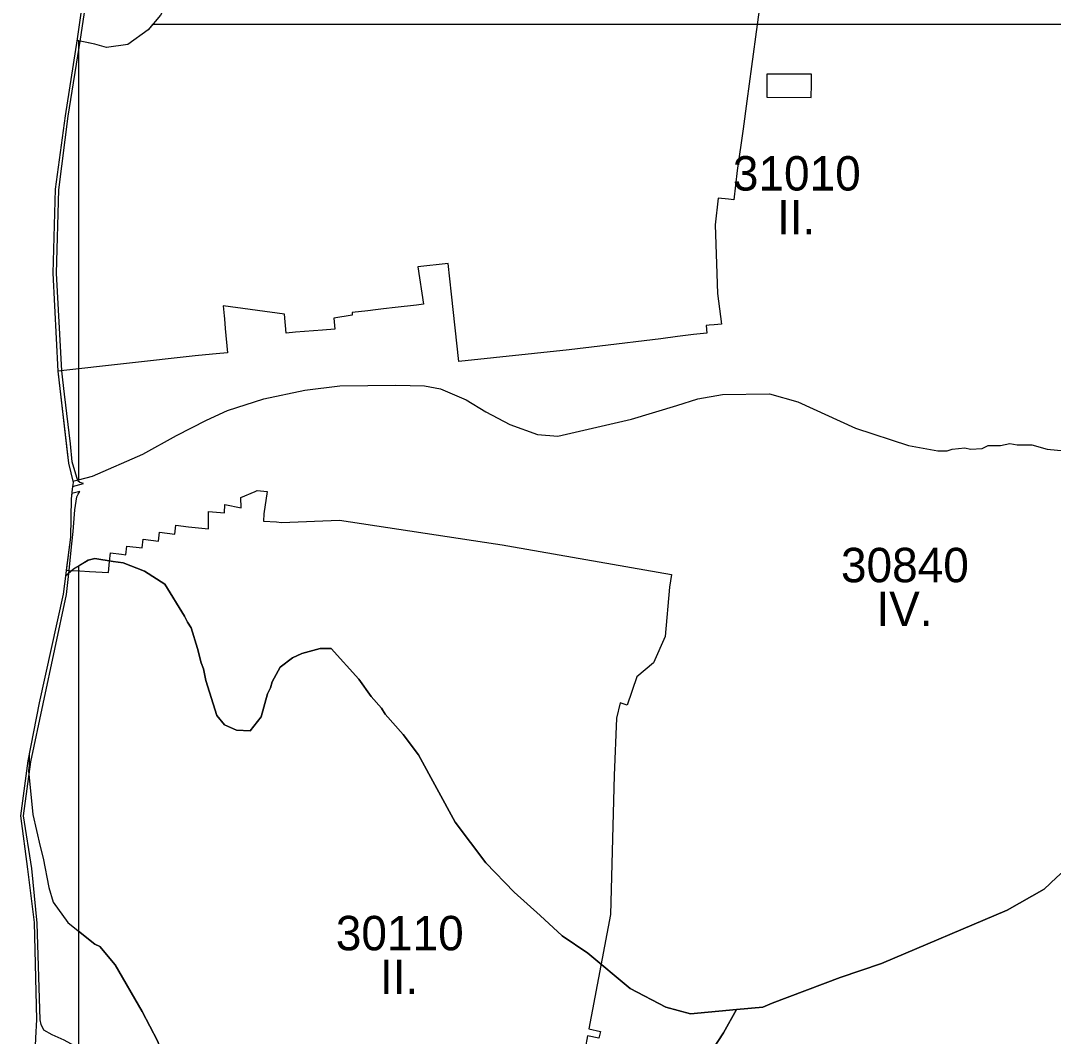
# Model space of a CAD drawing. Extents: x -555509 to -553014, y -1186753 to -1182560.
# Drawn here: x -555043 to -554443, y -1184853 to -1184262 of the extents above; entities that cross this region are included whole.
import ezdxf

# ---------------------------------------------------------------- set-up
doc = ezdxf.new("R2010")
doc.units = 0
for name, color, linetype in [('LEG_6_ZPF', 7, 'Continuous'), ('Level 29', 7, 'Continuous'), ('Level 52', 7, 'Continuous'), ('pěší_tr', 7, 'Continuous')]:
    doc.layers.add(name, color=color, linetype=linetype)

msp = doc.modelspace()

# ---------------------------------------------------------------- linework, layer by layer
at = {"layer": 'LEG_6_ZPF'}
for p, q in [((-554161.89, -1184264.77), (-554966.48, -1184264.77)), ((-555009.53, -1184274.13), (-555009.53, -1184529.34)), ((-555009.53, -1184579.45), (-555009.53, -1184791.53)), ((-555000, -1184799.13), (-555009.53, -1184791.53)), ((-555009.53, -1184791.53), (-555009.53, -1185173.66)), ((-554997, -1184800.62), (-555000, -1184799.13)), ((-554988.06, -1184811.25), (-554997, -1184800.62)), ((-554634.5, -1184850.75), (-554626.88, -1184837.12)), ((-554656.56, -1184884.62), (-554634.5, -1184850.75))]:
    msp.add_line(p, q, dxfattribs=at)
for points in [[(-554966.48, -1184264.77), (-554969, -1184267.75), (-554980.88, -1184276.25), (-554993.19, -1184278), (-555000, -1184276.13), (-555009.53, -1184274.13)], [(-555009.53, -1184529.34), (-555001.25, -1184527.25), (-554972, -1184514.5), (-554952.5, -1184503.5), (-554935.06, -1184494.63), (-554922.81, -1184489.12), (-554901.62, -1184482.25), (-554877.88, -1184477.25), (-554857.5, -1184474.63), (-554824.88, -1184474.25), (-554808.31, -1184474.63), (-554799, -1184476.38), (-554784.12, -1184482.75), (-554772.69, -1184489.88), (-554758.69, -1184497.12), (-554742.62, -1184503), (-554730.75, -1184503.88), (-554687.94, -1184494.13), (-554661.62, -1184486.13), (-554649.31, -1184482.25), (-554634.94, -1184479.75), (-554607.75, -1184479.38), (-554591.25, -1184484), (-554557.75, -1184499.25), (-554526.81, -1184509.38), (-554509.88, -1184512.38), (-554504.31, -1184512.38), (-554501.38, -1184511.5), (-554494.12, -1184510.75), (-554490.75, -1184511.5), (-554484, -1184511.13), (-554480.56, -1184509.38), (-554473.38, -1184509.38), (-554467.88, -1184508.12), (-554463.62, -1184509), (-554455.12, -1184509), (-554446.25, -1184511.5), (-554436.06, -1184512.38)], [(-554626.88, -1184837.12), (-554653.56, -1184839.75), (-554668, -1184835.88), (-554688.75, -1184824.88), (-554713.38, -1184804.5), (-554728.19, -1184794.38), (-554740.94, -1184782.5), (-554756.19, -1184768.88), (-554772.69, -1184751.88), (-554790.5, -1184728.25), (-554811.69, -1184689.13), (-554820.62, -1184677.38), (-554831.19, -1184665.5), (-554833.31, -1184662), (-554839.25, -1184655.25), (-554846.5, -1184645.13), (-554862.56, -1184627.25), (-554868.94, -1184627.25), (-554879.56, -1184630.25), (-554885.06, -1184632.75), (-554892.25, -1184638.25), (-554896.94, -1184646.75), (-554897.75, -1184650.12), (-554899.5, -1184653.62), (-554903.31, -1184667.12), (-554909.62, -1184675.25), (-554917.69, -1184674.75), (-554924.5, -1184671.75), (-554929.12, -1184666.25), (-554931.25, -1184659.5), (-554935.5, -1184646), (-554936.81, -1184639.12), (-554938.06, -1184635.75), (-554940.19, -1184627.25), (-554944, -1184615.38), (-554946.12, -1184612), (-554947.81, -1184608.63), (-554959.25, -1184590), (-554971.12, -1184582.38), (-554983.44, -1184577.62), (-554989.38, -1184576.88), (-555000, -1184575.13), (-555003.81, -1184576), (-555009.53, -1184579.45)], [(-554364, -1184690.88), (-554375, -1184701), (-554378.81, -1184703.12), (-554394.5, -1184709.13), (-554408.94, -1184719.75), (-554416.12, -1184728.25), (-554421.62, -1184736.63), (-554424.62, -1184743.5), (-554435.25, -1184755.38), (-554440.75, -1184760.38), (-554447.94, -1184767.25), (-554469.56, -1184779.5), (-554542.5, -1184810.5), (-554566.62, -1184818.5), (-554606.06, -1184833.38), (-554611.62, -1184835.88), (-554626.88, -1184837.12)], [(-555009.53, -1184791.53), (-555000, -1184799.13), (-554997, -1184800.62), (-554988.06, -1184811.25), (-554972.38, -1184838.38), (-554963.5, -1184855.38), (-554962.25, -1184858.75), (-554952.5, -1184874), (-554946.94, -1184884.25), (-554944.88, -1184889.25), (-554943.12, -1184892.75), (-554940.62, -1184898.63)], [(-554962.25, -1184858.75), (-554963.5, -1184855.38), (-554972.38, -1184838.38), (-554988.06, -1184811.25)], [(-554626.88, -1184837.12), (-554634.5, -1184850.75), (-554656.56, -1184884.62)]]:
    msp.add_lwpolyline(points, dxfattribs=at)
at = {"layer": 'Level 29'}
for points in [[(-554838, -1184075.75), (-554851.12, -1184084.63), (-554856.25, -1184089.63), (-554864.69, -1184101.5), (-554871.5, -1184115.12), (-554880, -1184135.5), (-554882.94, -1184145.63), (-554886.75, -1184155.88), (-554889.31, -1184160.88), (-554897.38, -1184172.75), (-554909.25, -1184188), (-554924.94, -1184203.25), (-554937.19, -1184220.25), (-554941, -1184227), (-554952.06, -1184244), (-554958, -1184252.5), (-554961.81, -1184259.25), (-554969, -1184267.75), (-554980.88, -1184276.25), (-554993.19, -1184278), (-555000, -1184276.13), (-555010.33, -1184273.96)], [(-555012.78, -1184530.16), (-555001.25, -1184527.25), (-554972, -1184514.5), (-554952.5, -1184503.5), (-554935.06, -1184494.63), (-554922.81, -1184489.12), (-554901.62, -1184482.25), (-554877.88, -1184477.25), (-554857.5, -1184474.63), (-554824.88, -1184474.25), (-554808.31, -1184474.63), (-554799, -1184476.38), (-554784.12, -1184482.75), (-554772.69, -1184489.88), (-554758.69, -1184497.12), (-554742.62, -1184503), (-554730.75, -1184503.88), (-554687.94, -1184494.13), (-554661.62, -1184486.13), (-554649.31, -1184482.25), (-554634.94, -1184479.75), (-554607.75, -1184479.38), (-554591.25, -1184484), (-554557.75, -1184499.25), (-554526.81, -1184509.38), (-554509.88, -1184512.38), (-554504.31, -1184512.38), (-554501.38, -1184511.5), (-554494.12, -1184510.75), (-554490.75, -1184511.5), (-554484, -1184511.13), (-554480.56, -1184509.38), (-554473.38, -1184509.38), (-554467.88, -1184508.12), (-554463.62, -1184509), (-554455.12, -1184509), (-554446.25, -1184511.5), (-554436.06, -1184512.38)], [(-555017.06, -1184585.21), (-555012.31, -1184581.12), (-555003.81, -1184576), (-555000, -1184575.13), (-554989.38, -1184576.88), (-554983.44, -1184577.62), (-554971.12, -1184582.38), (-554959.25, -1184590), (-554947.81, -1184608.63), (-554946.12, -1184612), (-554944, -1184615.38), (-554940.19, -1184627.25), (-554938.06, -1184635.75), (-554936.81, -1184639.12), (-554935.5, -1184646), (-554931.25, -1184659.5), (-554929.12, -1184666.25), (-554924.5, -1184671.75), (-554917.69, -1184674.75), (-554909.62, -1184675.25), (-554903.31, -1184667.12), (-554899.5, -1184653.62), (-554897.75, -1184650.12), (-554896.94, -1184646.75), (-554892.25, -1184638.25), (-554885.06, -1184632.75), (-554879.56, -1184630.25), (-554868.94, -1184627.25), (-554862.56, -1184627.25), (-554846.5, -1184645.13), (-554839.25, -1184655.25), (-554833.31, -1184662), (-554831.19, -1184665.5), (-554820.62, -1184677.38), (-554811.69, -1184689.13), (-554790.5, -1184728.25), (-554772.69, -1184751.88), (-554756.19, -1184768.88), (-554740.94, -1184782.5), (-554728.19, -1184794.38), (-554713.38, -1184804.5), (-554688.75, -1184824.88), (-554668, -1184835.88), (-554653.56, -1184839.75), (-554626.88, -1184837.12)], [(-555038.12, -1184688.4), (-555038.12, -1184695.12), (-555038.56, -1184698.5), (-555036, -1184723.88), (-555031.75, -1184742.5), (-555030.06, -1184749.25), (-555026.69, -1184766.25), (-555024.12, -1184774.75), (-555015.69, -1184786.63), (-555000, -1184799.13), (-554997, -1184800.62), (-554988.06, -1184811.25), (-554972.38, -1184838.38), (-554963.5, -1184855.38), (-554962.25, -1184858.75), (-554952.5, -1184874), (-554946.94, -1184884.25), (-554944.88, -1184889.25), (-554943.12, -1184892.75), (-554940.62, -1184898.63)], [(-554626.88, -1184837.12), (-554611.62, -1184835.88), (-554606.06, -1184833.38), (-554566.62, -1184818.5), (-554542.5, -1184810.5), (-554469.56, -1184779.5), (-554447.94, -1184767.25), (-554440.75, -1184760.38), (-554435.25, -1184755.38), (-554424.62, -1184743.5), (-554421.62, -1184736.63), (-554416.12, -1184728.25), (-554408.94, -1184719.75), (-554394.5, -1184709.13), (-554378.81, -1184703.12), (-554375, -1184701), (-554364, -1184690.88)], [(-554626.88, -1184837.12), (-554634.5, -1184850.75), (-554656.56, -1184884.62)]]:
    msp.add_lwpolyline(points, dxfattribs=at)
at = {"layer": 'Level 52'}
for points in [[(-554597.59, -1184220.73), (-554608.89, -1184220.71), (-554610.79, -1184234.99), (-554612.67, -1184249.06), (-554614.83, -1184264.68), (-554618.1, -1184289.13), (-554620.78, -1184309.35), (-554623.01, -1184325.33), (-554626.42, -1184349.54), (-554628.5, -1184366.61)], [(-554583.35, -1184299.38), (-554583.32, -1184293.58), (-554609.22, -1184293.47), (-554609.28, -1184306.97), (-554583.38, -1184307.08), (-554583.35, -1184299.38)], [(-554628.5, -1184366.61), (-554631.51, -1184366.27), (-554637.47, -1184365.6), (-554639.28, -1184381.15), (-554638.44, -1184403.84), (-554637.94, -1184420.98), (-554635.54, -1184438.95), (-554639.94, -1184439.16), (-554642.71, -1184439.5), (-554644.5, -1184439.63), (-554644.06, -1184444.05), (-554651.87, -1184444.95), (-554661.09, -1184446.08), (-554670.78, -1184447.34), (-554706.42, -1184451.63), (-554724.18, -1184453.83), (-554788.3, -1184460.55), (-554792.53, -1184421.4), (-554794.47, -1184403.51), (-554812.15, -1184405.49), (-554808.84, -1184427.26), (-554813.02, -1184427.75), (-554825.4, -1184429.2), (-554832.16, -1184429.99), (-554836.85, -1184430.55), (-554841.29, -1184431.07), (-554850.41, -1184432.14), (-554850.29, -1184433.72), (-554861.02, -1184435.36), (-554860.52, -1184441.79), (-554867.61, -1184442.33), (-554883.32, -1184443.52), (-554888.8, -1184444.04), (-554889.77, -1184432.98), (-554925.29, -1184428.22), (-554924.8, -1184434.01), (-554924.65, -1184435.72), (-554924.15, -1184441.36), (-554922.9, -1184455.52), (-554929.41, -1184456.14), (-554939.69, -1184457.11), (-554941.7, -1184457.31), (-555021.51, -1184466.21), (-555015.32, -1184519.62), (-555012.62, -1184530.82), (-555012.91, -1184533.21), (-555013.31, -1184536.45), (-555013.8, -1184540.42), (-555014.13, -1184562.57), (-555016.63, -1184581.86), (-555014.95, -1184581.95), (-555008.69, -1184582.29), (-555002.99, -1184582.59), (-554992.1, -1184583.16), (-554991.37, -1184576.88), (-554990.79, -1184571.82), (-554984.43, -1184572.58), (-554981.88, -1184572.89), (-554981.31, -1184567.79), (-554972.38, -1184568.9), (-554971.84, -1184563.76), (-554962.89, -1184564.91), (-554962.36, -1184559.74), (-554953.39, -1184560.92), (-554952.89, -1184555.71), (-554945.57, -1184556.55), (-554943.55, -1184556.78), (-554933.91, -1184557.88), (-554933.92, -1184555.43), (-554933.92, -1184554.33), (-554933.92, -1184552.75), (-554933.94, -1184547.65), (-554924.57, -1184548.52), (-554924.46, -1184543.63), (-554914.94, -1184545.54), (-554914.99, -1184539.6), (-554906.81, -1184536.13), (-554905.51, -1184535.57), (-554899.81, -1184536.15), (-554901.8, -1184549.08), (-554901.87, -1184553.35), (-554894.33, -1184553.82), (-554891.41, -1184554.08), (-554857.78, -1184552.7), (-554766.99, -1184566.47), (-554763.08, -1184567.16), (-554756.45, -1184568.21), (-554664.62, -1184584.28), (-554665.78, -1184591.72), (-554668.37, -1184620.38), (-554675.11, -1184635.77), (-554684.77, -1184643.87), (-554690.37, -1184660.23)], [(-554690.37, -1184660.23), (-554694.47, -1184658.87), (-554696.6, -1184667.81), (-554697.96, -1184701.13), (-554700.16, -1184781.85), (-554712.7, -1184848.47), (-554706.04, -1184849.97), (-554706.92, -1184853.88), (-554713.44, -1184852.4), (-554717.6, -1184874.5)]]:
    msp.add_lwpolyline(points, dxfattribs=at)
at = {"layer": 'pěší_tr'}
for points in [[(-555002.02, -1184215.93), (-555010.19, -1184272.95), (-555017.27, -1184317.79), (-555022.95, -1184360.44), (-555024.33, -1184409.14), (-555021.51, -1184466.21), (-555015.85, -1184515.06), (-555015.32, -1184519.62), (-555012.62, -1184530.82), (-555012.91, -1184533.21), (-555006.49, -1184531.46), (-555008.66, -1184530.81), (-555009.81, -1184529.83), (-555013.14, -1184518.86), (-555014.19, -1184508.49), (-555017.69, -1184479.59), (-555018.65, -1184471.18), (-555019.26, -1184465.9), (-555022.34, -1184409.18), (-555020.93, -1184360.76), (-555015.55, -1184317.88), (-555008.27, -1184273.24), (-554999.82, -1184216.47)], [(-555024.85, -1184851.88), (-555029.68, -1184849.21), (-555031.23, -1184845.94), (-555031.78, -1184843.13), (-555033.56, -1184786.91), (-555036.69, -1184755.24), (-555041.51, -1184724.58), (-555037.18, -1184693.13), (-555030.02, -1184659.42), (-555016.41, -1184595.94), (-555014.95, -1184581.95), (-555013.73, -1184570.27), (-555012.55, -1184559.33), (-555011.59, -1184546.69), (-555010.47, -1184539.2), (-555009.7, -1184537.57), (-555008.69, -1184536.09)], [(-555008.69, -1184536.09), (-555013.41, -1184537.28)], [(-555013.41, -1184537.28), (-555013.8, -1184540.42), (-555014.13, -1184562.57), (-555018.42, -1184595.69), (-555032.26, -1184659), (-555038.96, -1184692.59), (-555043.11, -1184724.5)], [(-555043.11, -1184724.5), (-555039.16, -1184755.62), (-555035.24, -1184786.57), (-555033.83, -1184842.95), (-555034.44, -1184853.76), (-555037.85, -1184932.48), (-555037.67, -1185040.6)], [(-555011.71, -1184858.22), (-555017.83, -1184854.96), (-555024.85, -1184851.88)]]:
    msp.add_lwpolyline(points, dxfattribs=at)

# ---------------------------------------------------------------- texts
at = {"layer": 'Level 29'}
for s, p in [('31010', (-554629, -1184361.2)), ('II.', (-554603.33, -1184386.66)), ('30840', (-554566.14, -1184588.84)), ('IV.', (-554545.56, -1184614.29)), ('30110', (-554859.87, -1184802.73)), ('II.', (-554834.2, -1184828.18))]:
    msp.add_text(s, height=20, dxfattribs=at).set_placement(p)

doc.saveas('drawing.dxf')
